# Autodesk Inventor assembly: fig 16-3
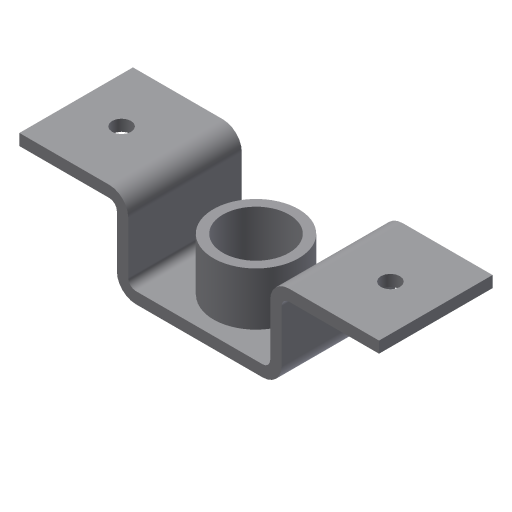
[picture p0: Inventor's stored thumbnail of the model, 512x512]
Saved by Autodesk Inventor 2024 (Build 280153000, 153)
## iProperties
Created: 2004-07
Part Number: fig 16-3
Document SubType Name: Weldment
Designer: CADCIM Technologies
Manufacturer: Standard
Standards Organization: Custom
Author: CADCIM Technologies
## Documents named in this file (3)
- D:\PROJECTS\Project 2023\RESOURCES INVENTOR 2024\RESOURCES INVENTOR 2024\Inventor_2023_Part\Inventor_2024_Part\c16_Inv_2024_prt\fig 16-3.iam
- D:\PROJECTS\Project 2023\RESOURCES INVENTOR 2024\RESOURCES INVENTOR 2024\Inventor_2023_Part\Inventor_2024_Part\c16_Inv_2024_prt\Bracket.ipt
- D:\PROJECTS\Project 2023\RESOURCES INVENTOR 2024\RESOURCES INVENTOR 2024\Inventor_2023_Part\Inventor_2024_Part\c16_Inv_2024_prt\cylinder.ipt
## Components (2 placed, 2 different names)
1. Bracket:1 — Insert:1
2. cylinder:1 — Insert:1
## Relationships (1: Insert 1)
- Insert:1: Bracket:1 ↔ cylinder:1
